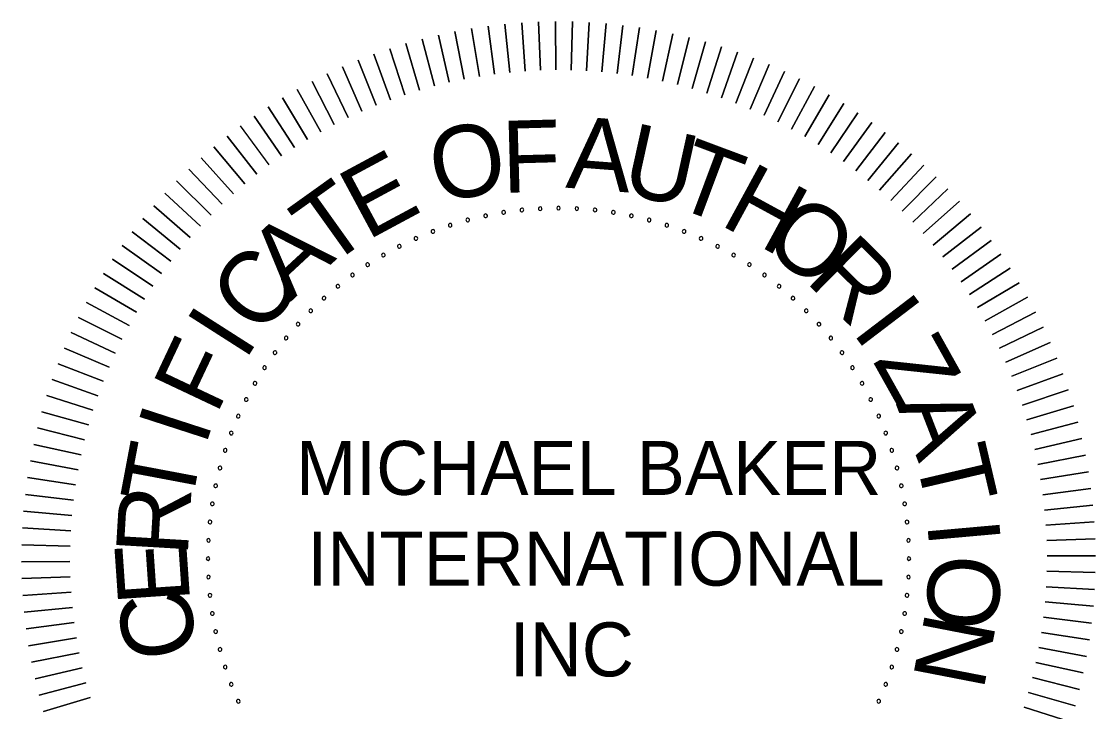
# Model space of a CAD drawing. Extents: x 164 to 3385, y 68 to 2119.
# Drawn here: x 2722.9 to 2971.7, y 530.6 to 690.4 of the extents above; entities that cross this region are included whole.
import ezdxf

# ---------------------------------------------------------------- set-up
doc = ezdxf.new("R2010")
doc.units = 0
doc.layers.add('G-ANNO-TEXT', color=7, linetype='Continuous')

msp = doc.modelspace()

# ---------------------------------------------------------------- linework, layer by layer
at = {"layer": 'G-ANNO-TEXT'}
for points in [[(2836.02, 678.61), (2834.9, 689.77)], [(2834.9, 689.77), (2836.02, 678.61)], [(2839.57, 678.91), (2838.8, 690.1)], [(2838.8, 690.1), (2839.57, 678.91)], [(2843.12, 679.09), (2842.7, 690.31)], [(2842.7, 690.31), (2843.12, 679.09)], [(2846.67, 679.17), (2846.61, 690.39)], [(2846.61, 690.39), (2846.67, 679.17)], [(2850.23, 679.13), (2850.52, 690.35)], [(2850.52, 690.35), (2850.23, 679.13)], [(2853.78, 678.98), (2854.43, 690.19)], [(2854.43, 690.19), (2853.78, 678.98)], [(2857.33, 678.73), (2858.33, 689.9)], [(2858.33, 689.9), (2857.33, 678.73)], [(2860.87, 678.35), (2862.21, 689.5)], [(2862.21, 689.5), (2860.87, 678.35)], [(2821.99, 676.3), (2819.48, 687.24)], [(2819.48, 687.24), (2821.99, 676.3)], [(2825.47, 677.05), (2823.31, 688.06)], [(2823.31, 688.06), (2825.47, 677.05)], [(2828.97, 677.68), (2827.15, 688.75)], [(2827.15, 688.75), (2828.97, 677.68)], [(2832.49, 678.2), (2831.02, 689.32)], [(2831.02, 689.32), (2832.49, 678.2)], [(2864.39, 677.87), (2866.09, 688.97)], [(2866.09, 688.97), (2864.39, 677.87)], [(2867.9, 677.28), (2869.94, 688.32)], [(2869.94, 688.32), (2867.9, 677.28)], [(2871.39, 676.58), (2873.77, 687.55)], [(2873.77, 687.55), (2871.39, 676.58)], [(2815.11, 674.5), (2811.92, 685.26)], [(2811.92, 685.26), (2815.11, 674.5)], [(2818.54, 675.45), (2815.69, 686.31)], [(2815.69, 686.31), (2818.54, 675.45)], [(2874.85, 675.77), (2877.58, 686.65)], [(2877.58, 686.65), (2874.85, 675.77)], [(2878.29, 674.85), (2881.36, 685.64)], [(2881.36, 685.64), (2878.29, 674.85)], [(2881.69, 673.82), (2885.1, 684.51)], [(2885.1, 684.51), (2881.69, 673.82)], [(2808.36, 672.26), (2804.5, 682.8)], [(2804.5, 682.8), (2808.36, 672.26)], [(2811.72, 673.43), (2808.19, 684.09)], [(2808.19, 684.09), (2811.72, 673.43)], [(2885.06, 672.69), (2888.8, 683.27)], [(2888.8, 683.27), (2885.06, 672.69)], [(2801.76, 669.61), (2797.25, 679.88)], [(2797.25, 679.88), (2801.76, 669.61)], [(2805.04, 670.99), (2800.85, 681.4)], [(2800.85, 681.4), (2805.04, 670.99)], [(2888.4, 671.45), (2892.47, 681.91)], [(2892.47, 681.91), (2888.4, 671.45)], [(2891.69, 670.11), (2896.09, 680.43)], [(2896.09, 680.43), (2891.69, 670.11)], [(2798.53, 668.12), (2793.69, 678.25)], [(2793.69, 678.25), (2798.53, 668.12)], [(2894.94, 668.66), (2899.66, 678.84)], [(2899.66, 678.84), (2894.94, 668.66)], [(2898.14, 667.12), (2903.18, 677.14)], [(2903.18, 677.14), (2898.14, 667.12)], [(2792.21, 664.86), (2786.75, 674.66)], [(2786.75, 674.66), (2792.21, 664.86)], [(2795.34, 666.54), (2790.19, 676.51)], [(2790.19, 676.51), (2795.34, 666.54)], [(2901.29, 665.47), (2906.65, 675.33)], [(2906.65, 675.33), (2901.29, 665.47)], [(2789.13, 663.08), (2783.36, 672.71)], [(2783.36, 672.71), (2789.13, 663.08)], [(2904.39, 663.72), (2910.05, 673.41)], [(2910.05, 673.41), (2904.39, 663.72)], [(2786.11, 661.21), (2780.04, 670.65)], [(2780.04, 670.65), (2786.11, 661.21)], [(2907.44, 661.88), (2913.4, 671.39)], [(2913.4, 671.39), (2907.44, 661.88)], [(2783.15, 659.24), (2776.79, 668.48)], [(2776.79, 668.48), (2783.15, 659.24)], [(2910.42, 659.95), (2916.68, 669.26)], [(2916.68, 669.26), (2910.42, 659.95)], [(2913.34, 657.92), (2919.89, 667.03)], [(2919.89, 667.03), (2913.34, 657.92)], [(2780.25, 657.18), (2773.6, 666.22)], [(2916.2, 655.8), (2923.03, 664.7)], [(2923.03, 664.7), (2916.2, 655.8)], [(2777.41, 655.02), (2770.49, 663.85)], [(2770.49, 663.85), (2777.41, 655.02)], [(2918.99, 653.59), (2926.09, 662.28)], [(2926.09, 662.28), (2918.99, 653.59)], [(2774.65, 652.78), (2767.45, 661.39)], [(2767.45, 661.39), (2774.65, 652.78)], [(2921.7, 651.29), (2929.08, 659.75)], [(2929.08, 659.75), (2921.7, 651.29)], [(2771.96, 650.46), (2764.49, 658.84)], [(2764.49, 658.84), (2771.96, 650.46)], [(2931.98, 657.14), (2924.35, 648.92)], [(2924.35, 648.92), (2931.98, 657.14)], [(2769.34, 648.05), (2761.61, 656.19)], [(2761.61, 656.19), (2769.34, 648.05)], [(2766.8, 645.56), (2758.82, 653.45)], [(2758.82, 653.45), (2766.8, 645.56)], [(2934.81, 654.43), (2926.92, 646.45)], [(2926.92, 646.45), (2934.81, 654.43)], [(2764.34, 642.99), (2756.12, 650.63)], [(2756.12, 650.63), (2764.34, 642.99)], [(2937.54, 651.64), (2929.4, 643.91)], [(2929.4, 643.91), (2937.54, 651.64)], [(2761.96, 640.35), (2753.5, 647.72)], [(2753.5, 647.72), (2761.96, 640.35)], [(2940.19, 648.77), (2931.81, 641.3)], [(2931.81, 641.3), (2940.19, 648.77)], [(2759.67, 637.63), (2750.98, 644.74)], [(2750.98, 644.74), (2759.67, 637.63)], [(2942.74, 645.81), (2934.14, 638.61)], [(2934.14, 638.61), (2942.74, 645.81)], [(2945.21, 642.77), (2936.38, 635.84)], [(2936.38, 635.84), (2945.21, 642.77)], [(2757.46, 634.84), (2748.55, 641.67)], [(2748.55, 641.67), (2757.46, 634.84)], [(2947.57, 639.66), (2938.53, 633.01)], [(2938.53, 633.01), (2947.57, 639.66)], [(2755.34, 631.99), (2746.22, 638.53)], [(2746.22, 638.53), (2755.34, 631.99)], [(2753.31, 629.07), (2743.99, 635.32)], [(2743.99, 635.32), (2753.31, 629.07)], [(2949.84, 636.47), (2940.59, 630.11)], [(2940.59, 630.11), (2949.84, 636.47)], [(2952, 633.22), (2942.56, 627.15)], [(2942.56, 627.15), (2952, 633.22)], [(2751.37, 626.08), (2741.87, 632.04)], [(2741.87, 632.04), (2751.37, 626.08)], [(2954.06, 629.89), (2944.43, 624.13)], [(2944.43, 624.13), (2954.06, 629.89)], [(2749.53, 623.04), (2739.84, 628.7)], [(2739.84, 628.7), (2749.53, 623.04)], [(2747.79, 619.94), (2737.92, 625.29)], [(2737.92, 625.29), (2747.79, 619.94)], [(2956.02, 626.51), (2946.21, 621.05)], [(2946.21, 621.05), (2956.02, 626.51)], [(2957.87, 623.06), (2947.9, 617.91)], [(2947.9, 617.91), (2957.87, 623.06)], [(2746.14, 616.79), (2736.11, 621.83)], [(2736.11, 621.83), (2746.14, 616.79)], [(2744.59, 613.59), (2734.41, 618.31)], [(2734.41, 618.31), (2744.59, 613.59)], [(2959.61, 619.56), (2949.48, 614.73)], [(2949.48, 614.73), (2959.61, 619.56)], [(2743.15, 610.34), (2732.82, 614.74)], [(2732.82, 614.74), (2743.15, 610.34)], [(2961.23, 616.01), (2950.96, 611.49)], [(2950.96, 611.49), (2961.23, 616.01)], [(2962.75, 612.41), (2952.34, 608.22)], [(2952.34, 608.22), (2962.75, 612.41)], [(2741.81, 607.04), (2731.35, 611.12)], [(2731.35, 611.12), (2741.81, 607.04)], [(2740.57, 603.71), (2729.99, 607.45)], [(2729.99, 607.45), (2740.57, 603.71)], [(2964.15, 608.76), (2953.61, 604.9)], [(2953.61, 604.9), (2964.15, 608.76)], [(2965.44, 605.07), (2954.79, 601.54)], [(2954.79, 601.54), (2965.44, 605.07)], [(2739.43, 600.34), (2728.74, 603.75)], [(2728.74, 603.75), (2739.43, 600.34)], [(2738.41, 596.93), (2727.61, 600)], [(2727.61, 600), (2738.41, 596.93)], [(2966.61, 601.34), (2955.85, 598.14)], [(2955.85, 598.14), (2966.61, 601.34)], [(2967.66, 597.57), (2956.81, 594.72)], [(2956.81, 594.72), (2967.66, 597.57)], [(2737.49, 593.5), (2726.6, 596.23)], [(2726.6, 596.23), (2737.49, 593.5)], [(2736.68, 590.03), (2725.71, 592.42)], [(2725.71, 592.42), (2736.68, 590.03)], [(2968.6, 593.77), (2957.66, 591.26)], [(2957.66, 591.26), (2968.6, 593.77)], [(2969.41, 589.95), (2958.4, 587.79)], [(2958.4, 587.79), (2969.41, 589.95)], [(2735.98, 586.55), (2724.94, 588.59)], [(2724.94, 588.59), (2735.98, 586.55)], [(2970.1, 586.1), (2959.03, 584.29)], [(2959.03, 584.29), (2970.1, 586.1)], [(2735.38, 583.04), (2724.29, 584.73)], [(2724.29, 584.73), (2735.38, 583.04)], [(2734.9, 579.52), (2723.76, 580.86)], [(2723.76, 580.86), (2734.9, 579.52)], [(2970.68, 582.24), (2959.55, 580.77)], [(2959.55, 580.77), (2970.68, 582.24)], [(2971.13, 578.35), (2959.96, 577.23)], [(2959.96, 577.23), (2971.13, 578.35)], [(2734.53, 575.98), (2723.35, 576.97)], [(2723.35, 576.97), (2734.53, 575.98)], [(2734.27, 572.43), (2723.07, 573.07)], [(2723.07, 573.07), (2734.27, 572.43)], [(2971.46, 574.46), (2960.26, 573.69)], [(2960.26, 573.69), (2971.46, 574.46)], [(2971.66, 570.55), (2960.45, 570.14)], [(2960.45, 570.14), (2971.66, 570.55)], [(2734.12, 568.88), (2722.91, 569.17)], [(2722.91, 569.17), (2734.12, 568.88)], [(2734.09, 565.32), (2722.87, 565.26)], [(2722.87, 565.26), (2734.09, 565.32)], [(2971.74, 566.65), (2960.52, 566.58)], [(2960.52, 566.58), (2971.74, 566.65)], [(2971.7, 562.74), (2960.49, 563.03)], [(2960.49, 563.03), (2971.7, 562.74)], [(2734.16, 561.76), (2722.95, 561.35)], [(2722.95, 561.35), (2734.16, 561.76)], [(2734.35, 558.21), (2723.15, 557.45)], [(2723.15, 557.45), (2734.35, 558.21)], [(2971.54, 558.83), (2960.34, 559.47)], [(2960.34, 559.47), (2971.54, 558.83)], [(2971.26, 554.93), (2960.08, 555.93)], [(2960.08, 555.93), (2971.26, 554.93)], [(2734.65, 554.67), (2723.48, 553.55)], [(2723.48, 553.55), (2734.65, 554.67)], [(2735.06, 551.14), (2723.93, 549.67)], [(2723.93, 549.67), (2735.06, 551.14)], [(2970.85, 551.04), (2959.71, 552.39)], [(2959.71, 552.39), (2970.85, 551.04)], [(2735.58, 547.62), (2724.51, 545.8)], [(2724.51, 545.8), (2735.58, 547.62)], [(2970.32, 547.17), (2959.23, 548.86)], [(2959.23, 548.86), (2970.32, 547.17)], [(2969.67, 543.32), (2958.63, 545.36)], [(2958.63, 545.36), (2969.67, 543.32)], [(2736.21, 544.12), (2725.2, 541.95)], [(2725.2, 541.95), (2736.21, 544.12)], [(2736.95, 540.64), (2726.01, 538.13)], [(2726.01, 538.13), (2736.95, 540.64)], [(2968.9, 539.48), (2957.93, 541.87)], [(2957.93, 541.87), (2968.9, 539.48)], [(2968.01, 535.68), (2957.12, 538.41)], [(2957.12, 538.41), (2968.01, 535.68)], [(2737.8, 537.18), (2726.95, 534.33)], [(2726.95, 534.33), (2737.8, 537.18)], [(2738.76, 533.76), (2728, 530.57)], [(2728, 530.57), (2738.76, 533.76)], [(2967, 531.9), (2956.2, 534.97)], [(2956.2, 534.97), (2967, 531.9)], [(2965.87, 528.16), (2955.18, 531.57)], [(2955.18, 531.57), (2965.87, 528.16)]]:
    msp.add_lwpolyline(points, dxfattribs=at)
for centre, start, end in [((2838.82, 646.72), 6, 186), ((2843.05, 647.06), 3, 183), ((2847.3, 647.17), 0, 180), ((2847.3, 647.17), 180, 0), ((2851.56, 647.06), 357, 177), ((2855.79, 646.72), 354, 174), ((2826.28, 644.4), 15, 195), ((2830.42, 645.39), 12, 192), ((2830.42, 645.39), 192, 12), ((2834.6, 646.17), 9, 189), ((2834.6, 646.17), 189, 9), ((2838.82, 646.72), 186, 6), ((2843.05, 647.06), 183, 3), ((2851.56, 647.06), 177, 357), ((2855.79, 646.72), 174, 354), ((2860.01, 646.17), 171, 351), ((2860.01, 646.17), 351, 171), ((2864.19, 645.39), 168, 348), ((2864.19, 645.39), 348, 168), ((2868.32, 644.4), 345, 165), ((2818.2, 641.77), 21, 201), ((2822.21, 643.19), 18, 198), ((2822.21, 643.19), 198, 18), ((2826.28, 644.4), 195, 15), ((2868.32, 644.4), 165, 345), ((2872.4, 643.19), 162, 342), ((2872.4, 643.19), 342, 162), ((2876.41, 641.77), 339, 159), ((2814.27, 640.15), 24, 204), ((2814.27, 640.15), 204, 24), ((2818.2, 641.77), 201, 21), ((2876.41, 641.77), 159, 339), ((2880.34, 640.15), 156, 336), ((2880.34, 640.15), 336, 156), ((2810.43, 638.31), 27, 207), ((2810.43, 638.31), 207, 27), ((2884.18, 638.31), 153, 333), ((2884.18, 638.31), 333, 153), ((2806.7, 636.29), 30, 210), ((2806.7, 636.29), 210, 30), ((2887.91, 636.29), 150, 330), ((2887.91, 636.29), 330, 150), ((2803.07, 634.06), 33, 213), ((2803.07, 634.06), 213, 33), ((2891.54, 634.06), 147, 327), ((2891.54, 634.06), 327, 147), ((2799.57, 631.66), 36, 216), ((2799.57, 631.66), 216, 36), ((2895.04, 631.66), 144, 324), ((2895.04, 631.66), 324, 144), ((2796.19, 629.07), 39, 219), ((2796.19, 629.07), 219, 39), ((2898.42, 629.07), 141, 321), ((2898.42, 629.07), 321, 141), ((2792.96, 626.31), 42, 222), ((2792.96, 626.31), 222, 42), ((2901.65, 626.31), 138, 318), ((2901.65, 626.31), 318, 138), ((2789.88, 623.38), 45, 225), ((2789.88, 623.38), 225, 45), ((2904.73, 623.38), 135, 315), ((2904.73, 623.38), 315, 135), ((2786.95, 620.29), 48, 228), ((2786.95, 620.29), 228, 48), ((2907.66, 620.29), 132, 312), ((2907.66, 620.29), 312, 132), ((2784.19, 617.06), 51, 231), ((2784.19, 617.06), 231, 51), ((2910.42, 617.06), 129, 309), ((2910.42, 617.06), 309, 129), ((2781.6, 613.69), 54, 234), ((2781.6, 613.69), 234, 54), ((2913.01, 613.69), 126, 306), ((2913.01, 613.69), 306, 126), ((2779.19, 610.18), 57, 237), ((2779.19, 610.18), 237, 57), ((2915.42, 610.18), 123, 303), ((2915.42, 610.18), 303, 123), ((2776.97, 606.56), 60, 240), ((2776.97, 606.56), 240, 60), ((2917.64, 606.56), 120, 300), ((2917.64, 606.56), 300, 120), ((2774.94, 602.82), 63, 243), ((2774.94, 602.82), 243, 63), ((2919.67, 602.82), 117, 297), ((2919.67, 602.82), 297, 117), ((2773.11, 598.98), 66, 246), ((2773.11, 598.98), 246, 66), ((2921.5, 598.98), 114, 294), ((2921.5, 598.98), 294, 114), ((2771.48, 595.06), 69, 249), ((2771.48, 595.06), 249, 69), ((2923.13, 595.06), 111, 291), ((2923.13, 595.06), 291, 111), ((2770.07, 591.05), 72, 252), ((2770.07, 591.05), 252, 72), ((2924.54, 591.05), 108, 288), ((2924.54, 591.05), 288, 108), ((2768.86, 586.97), 75, 255), ((2768.86, 586.97), 255, 75), ((2925.75, 586.97), 105, 285), ((2925.75, 586.97), 285, 105), ((2767.86, 582.84), 78, 258), ((2767.86, 582.84), 258, 78), ((2926.74, 582.84), 102, 282), ((2926.74, 582.84), 282, 102), ((2767.09, 578.66), 81, 261), ((2767.09, 578.66), 261, 81), ((2927.52, 578.66), 99, 279), ((2927.52, 578.66), 279, 99), ((2766.54, 574.44), 84, 264), ((2766.54, 574.44), 264, 84), ((2928.07, 574.44), 96, 276), ((2928.07, 574.44), 276, 96), ((2766.2, 570.2), 87, 267), ((2766.2, 570.2), 267, 87), ((2928.41, 570.2), 93, 273), ((2928.41, 570.2), 273, 93), ((2766.09, 565.95), 90, 270), ((2766.09, 565.95), 270, 90), ((2928.52, 565.95), 90, 270), ((2928.52, 565.95), 270, 90), ((2766.2, 561.7), 93, 273), ((2766.2, 561.7), 273, 93), ((2928.41, 561.7), 87, 267), ((2928.41, 561.7), 267, 87), ((2766.54, 557.46), 96, 276), ((2766.54, 557.46), 276, 96), ((2928.07, 557.46), 84, 264), ((2928.07, 557.46), 264, 84), ((2767.09, 553.25), 99, 279), ((2767.09, 553.25), 279, 99), ((2927.52, 553.25), 81, 261), ((2927.52, 553.25), 261, 81), ((2767.86, 549.07), 102, 282), ((2767.86, 549.07), 282, 102), ((2926.74, 549.07), 78, 258), ((2926.74, 549.07), 258, 78), ((2768.86, 544.93), 105, 285), ((2768.86, 544.93), 285, 105), ((2925.75, 544.93), 75, 255), ((2925.75, 544.93), 255, 75), ((2770.07, 540.85), 108, 288), ((2770.07, 540.85), 288, 108), ((2924.54, 540.85), 72, 252), ((2924.54, 540.85), 252, 72), ((2771.48, 536.85), 111, 291), ((2771.48, 536.85), 291, 111), ((2923.13, 536.85), 69, 249), ((2923.13, 536.85), 249, 69), ((2773.11, 532.92), 114, 294), ((2773.11, 532.92), 294, 114), ((2921.5, 532.92), 66, 246), ((2921.5, 532.92), 246, 66)]:
    msp.add_arc(centre, 0.417, start, end, dxfattribs=at)

# ---------------------------------------------------------------- texts
for s, rotation, p in [('F', 1.5867, (2834.37, 650.68)), ('A', 355.5955, (2848.82, 651.91)), ('O', 10.7295, (2819.15, 648.28)), ('U', 347.5481, (2861.43, 650.72)), ('T', 339.5007, (2873.07, 647.94)), ('E', 28.279, (2802.96, 639.55)), ('H', 331.4533, (2884.37, 643.48)), ('T', 35.5725, (2793.66, 633.09)), ('O', 323.4059, (2893.94, 638.21)), ('A', 42.8659, (2785.19, 625.39)), ('R', 315.3585, (2904.27, 630.31)), ('C', 50.1594, (2778.18, 617.06)), ('I', 307.3112, (2915.11, 618.57)), ('I', 57.4529, (2774.56, 611.49)), ('F', 64.7464, (2768.02, 599.02)), ('Z', 299.2638, (2920, 611.78)), ('I', 72.0398, (2765.44, 591.7)), ('A', 291.2164, (2925.47, 601.75)), ('T', 79.3333, (2762.12, 577.34)), ('T', 283.169, (2929.82, 589.96)), ('R', 86.6268, (2761.36, 566.32)), ('I', 275.1216, (2932.71, 574.36)), ('E', 93.9203, (2761.97, 555.91)), ('O', 267.0743, (2933.3, 567.2)), ('C', 101.2137, (2764.1, 544.32)), ('N', 259.0269, (2932.42, 554.09))]:
    msp.add_text(s, height=16.67, rotation=rotation, dxfattribs=at).set_placement(p)
for s, height, p in [('MICHAEL BAKER', 12.5016, (2786.48, 580.73)), (' INTERNATIONAL', 12.5016, (2784.47, 559.71)), ('INC', 12.502, (2835.98, 538.69))]:
    msp.add_text(s, height=height, dxfattribs=at).set_placement(p)

doc.saveas('drawing.dxf')
